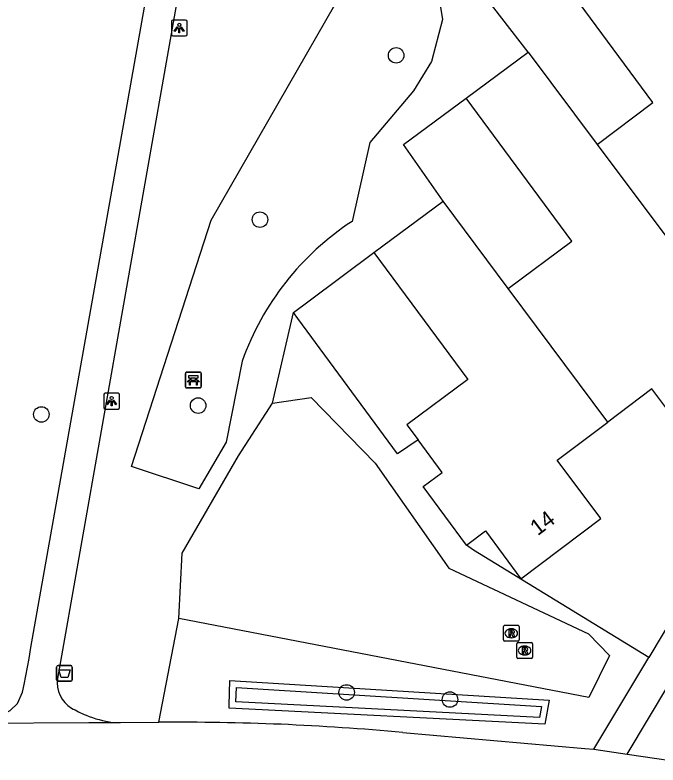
# Model space of a CAD drawing. Extents: x 163427 to 164190, y 380331 to 381641.
# Drawn here: x 163844.72 to 163885.29, y 381011.84 to 381059.16 of the extents above; entities that cross this region are included whole.
import ezdxf

# ---------------------------------------------------------------- set-up
doc = ezdxf.new("R2010")
doc.units = 0
for name, color, linetype in [('IMGEO_Afvalbak', 7, 'Continuous'), ('IMGEO_Bank', 7, 'Continuous'), ('IMGEO_Boom', 7, 'Continuous'), ('IMGEO_Fietspad_gesloten', 7, 'Continuous'), ('IMGEO_Groenvoorziening', 7, 'Continuous'), ('IMGEO_Lichtpunt', 7, 'Continuous'), ('IMGEO_Meer_plas_ven_vijver', 7, 'Continuous'), ('IMGEO_Pand', 7, 'Continuous'), ('IMGEO_Pand_nummerreeks', 7, 'Continuous'), ('IMGEO_Rioolput', 7, 'Continuous'), ('IMGEO_Voetpad_halfverhard', 7, 'Continuous'), ('IMGEO_Voetpad_open', 7, 'Continuous'), ('IMGEO_Waterloop', 7, 'Continuous')]:
    doc.layers.add(name, color=color, linetype=linetype)

msp = doc.modelspace()

# ---------------------------------------------------------------- linework, layer by layer
at = {"layer": 'IMGEO_Afvalbak'}
for p, q in [((163847.344, 381017.217), (163847.344, 381018.017)), ((163847.344, 381018.017), (163847.344, 381017.217)), ((163847.444, 381018.117), (163848.234, 381018.117)), ((163848.234, 381018.117), (163847.444, 381018.117)), ((163848.334, 381018.017), (163848.334, 381017.217)), ((163848.334, 381017.217), (163848.334, 381018.017)), ((163848.234, 381017.117), (163847.444, 381017.117)), ((163847.444, 381017.117), (163848.234, 381017.117))]:
    msp.add_line(p, q, dxfattribs=at)
msp.add_lwpolyline([(163847.487, 381017.831), (163848.191, 381017.831), (163848.042, 381017.361), (163847.636, 381017.361), (163847.487, 381017.831)], dxfattribs=at)
for centre, start, end in [((163847.444, 381018.017), 90, 180), ((163847.444, 381018.017), 90, 180), ((163848.234, 381018.017), 0, 90), ((163848.234, 381018.017), 360, 90), ((163847.444, 381017.217), 180, 270), ((163847.444, 381017.217), 180, 270), ((163848.234, 381017.217), 270, 0), ((163848.234, 381017.217), 270, 0)]:
    msp.add_arc(centre, 0.1, start, end, dxfattribs=at)
at = {"layer": 'IMGEO_Bank'}
for p, q in [((163855.469, 381035.7), (163855.469, 381036.541)), ((163855.469, 381036.541), (163855.469, 381035.7)), ((163855.544, 381036.625), (163856.385, 381036.625)), ((163856.385, 381036.625), (163855.544, 381036.625)), ((163856.469, 381036.55), (163856.469, 381035.709)), ((163856.469, 381035.709), (163856.469, 381036.55)), ((163856.166, 381036.023), (163855.773, 381036.023)), ((163855.778, 381036.131), (163855.778, 381036.237)), ((163855.822, 381036.237), (163855.822, 381036.131)), ((163856.11, 381036.243), (163855.828, 381036.243)), ((163855.828, 381036.125), (163856.11, 381036.125)), ((163856.116, 381036.131), (163856.116, 381036.237)), ((163856.16, 381036.237), (163856.16, 381036.131)), ((163856.394, 381035.625), (163855.553, 381035.625)), ((163855.553, 381035.625), (163856.394, 381035.625))]:
    msp.add_line(p, q, dxfattribs=at)
for points in [[(163855.772, 381036.243), (163855.686, 381036.243), (163855.686, 381036.404), (163856.249, 381036.404), (163856.249, 381036.243), (163856.166, 381036.243)], [(163855.716, 381036.023), (163855.574, 381036.023), (163855.686, 381036.125), (163855.772, 381036.125)], [(163855.766, 381036.016), (163855.766, 381035.809), (163855.723, 381035.809), (163855.723, 381036.016)], [(163856.166, 381036.125), (163856.249, 381036.125), (163856.361, 381036.023), (163856.222, 381036.023)], [(163856.216, 381036.016), (163856.216, 381035.809), (163856.172, 381035.809), (163856.172, 381036.016)]]:
    msp.add_lwpolyline(points, dxfattribs=at)
for centre, radius, start, end in [((163855.547, 381036.547), 0.0779, 92.4484, 184.2845), ((163855.547, 381036.547), 0.0779, 92.4484, 184.2845), ((163856.391, 381036.547), 0.0779, 2.4484, 94.2845), ((163856.391, 381036.547), 0.0779, 2.4484, 94.2845), ((163855.716, 381036.016), 0.00671, 2.8957, 87.1043), ((163855.773, 381036.016), 0.00671, 92.8957, 177.1043), ((163855.771, 381036.236), 0.00671, 2.8957, 87.1043), ((163855.771, 381036.132), 0.00671, 272.8957, 357.1043), ((163855.828, 381036.236), 0.00671, 92.8957, 177.1043), ((163855.828, 381036.132), 0.00671, 182.8957, 267.1043), ((163856.11, 381036.236), 0.00671, 2.8957, 87.1043), ((163856.11, 381036.132), 0.00671, 272.8957, 357.1043), ((163856.167, 381036.236), 0.00671, 92.8957, 177.1043), ((163856.167, 381036.132), 0.00671, 182.8957, 267.1043), ((163856.165, 381036.016), 0.00671, 2.8957, 87.1043), ((163856.222, 381036.016), 0.00671, 92.8957, 177.1043), ((163855.547, 381035.703), 0.0779, 182.4484, 274.2845), ((163855.547, 381035.703), 0.0779, 182.4484, 274.2845), ((163856.391, 381035.703), 0.0779, 272.4484, 4.2845), ((163856.391, 381035.703), 0.0779, 272.4484, 4.2845)]:
    msp.add_arc(centre, radius, start, end, dxfattribs=at)
at = {"layer": 'IMGEO_Boom'}
for centre in [(163868.764, 381056.614), (163860.172, 381046.249), (163856.273, 381034.515), (163846.384, 381033.957), (163865.641, 381016.415), (163872.161, 381015.964)]:
    msp.add_circle(centre, 0.489, dxfattribs=at)
at = {"layer": 'IMGEO_Fietspad_gesloten'}
for points in [[(163842.404, 381014.476), (163849.374, 381014.508), (163850.868, 381014.515)], [(163850.868, 381014.515), (163851.377, 381014.517), (163853.795, 381014.528)], [(163869.192, 381013.882), (163880.671, 381012.884), (163881.243, 381012.828)], [(163881.243, 381012.828), (163883.348, 381012.515)], [(163883.348, 381012.515), (163887.945, 381011.835)]]:
    msp.add_lwpolyline(points, dxfattribs=at)
msp.add_arc((163855.187, 380863.887), 150.647, 84.66566, 90.52933, dxfattribs=at)
at = {"layer": 'IMGEO_Groenvoorziening'}
for points in [[(163892.032, 381091.103), (163892.433, 381091.325), (163893.363, 381089.769), (163893.712, 381086.589), (163885.188, 381079.149), (163877.401, 381069.894), (163877.35, 381068.327), (163876.539, 381066.473), (163872.253, 381063.156), (163871.244, 381061.59), (163871.684, 381058.886), (163871, 381056.23), (163869.868, 381054.37), (163867.112, 381051.126), (163865.984, 381046.133)], [(163877.091, 381056.827), (163873.767, 381061.119), (163873.306, 381061.714), (163874.824, 381062.84), (163881.373, 381067.697), (163879.447, 381070.311), (163879.387, 381070.393), (163879.593, 381070.547), (163883.835, 381073.718)], [(163859.052, 381037.328), (163858.039, 381032.201), (163856.309, 381029.254), (163852.062, 381030.665), (163857.097, 381046.206), (163865.555, 381060.95), (163867.201, 381064.226)], [(163871.728, 381047.42), (163869.236, 381050.985), (163873.193, 381053.924)], [(163862.281, 381040.382), (163863.274, 381041.124), (163867.363, 381044.182)], [(163860.955, 381034.673), (163862.281, 381040.382)], [(163870.145, 381032.362), (163868.85, 381031.479), (163862.563, 381040), (163862.281, 381040.382)], [(163884.702, 381018.618), (163873.638, 381025.391), (163873.196, 381025.711)], [(163853.795, 381014.528), (163855.057, 381021.071)], [(163878.156, 381014.406), (163858.232, 381015.424), (163858.238, 381015.621), (163858.281, 381017.177), (163878.428, 381015.916), (163878.156, 381014.406)]]:
    msp.add_lwpolyline(points, dxfattribs=at)
msp.add_arc((163875.638, 381031.401), 17.614, 123.2384, 160.3363, dxfattribs=at)
at = {"layer": 'IMGEO_Lichtpunt'}
for p, q in [((163854.583, 381058.744), (163854.583, 381057.937)), ((163854.583, 381058.744), (163854.583, 381057.937)), ((163855.485, 381058.839), (163854.677, 381058.839)), ((163855.485, 381058.839), (163854.677, 381058.839)), ((163855.579, 381057.937), (163855.579, 381058.744)), ((163855.579, 381057.937), (163855.579, 381058.744)), ((163854.677, 381057.843), (163855.485, 381057.843)), ((163854.677, 381057.843), (163855.485, 381057.843)), ((163850.316, 381035.196), (163850.316, 381034.389)), ((163850.316, 381035.196), (163850.316, 381034.389)), ((163851.218, 381035.291), (163850.41, 381035.291)), ((163851.218, 381035.291), (163850.41, 381035.291)), ((163851.312, 381034.389), (163851.312, 381035.196)), ((163851.312, 381034.389), (163851.312, 381035.196)), ((163850.41, 381034.295), (163851.218, 381034.295)), ((163850.41, 381034.295), (163851.218, 381034.295))]:
    msp.add_line(p, q, dxfattribs=at)
for points in [[(163854.957, 381058.408), (163854.996, 381058.38), (163854.808, 381058.118), (163854.77, 381058.145), (163854.957, 381058.408)], [(163855.059, 381058.36), (163855.106, 381058.36), (163855.106, 381058.038), (163855.059, 381058.038), (163855.059, 381058.36)], [(163855.169, 381058.38), (163855.207, 381058.407), (163855.394, 381058.145), (163855.355, 381058.117), (163855.169, 381058.38)], [(163850.69, 381034.86), (163850.729, 381034.832), (163850.541, 381034.57), (163850.503, 381034.597), (163850.69, 381034.86)], [(163850.792, 381034.812), (163850.839, 381034.812), (163850.839, 381034.49), (163850.792, 381034.49), (163850.792, 381034.812)], [(163850.902, 381034.832), (163850.94, 381034.859), (163851.127, 381034.597), (163851.088, 381034.569), (163850.902, 381034.832)]]:
    msp.add_lwpolyline(points, dxfattribs=at)
for centre in [(163855.082, 381058.542), (163850.815, 381034.994)]:
    msp.add_circle(centre, 0.0994, dxfattribs=at)
for centre, start, end in [((163854.677, 381058.744), 90, 180), ((163854.677, 381058.744), 90, 180), ((163855.485, 381058.744), 0, 90), ((163855.485, 381058.744), 0, 90), ((163854.677, 381057.937), 180, 270), ((163854.677, 381057.937), 180, 270), ((163855.485, 381057.937), 270, 0), ((163855.485, 381057.937), 270, 360), ((163850.41, 381035.196), 90, 180), ((163850.41, 381035.196), 90, 180), ((163851.218, 381035.196), 0, 90), ((163851.218, 381035.196), 0, 90), ((163850.41, 381034.389), 180, 270), ((163850.41, 381034.389), 180, 270), ((163851.218, 381034.389), 270, 0), ((163851.218, 381034.389), 270, 360)]:
    msp.add_arc(centre, 0.0946, start, end, dxfattribs=at)
at = {"layer": 'IMGEO_Meer_plas_ven_vijver'}
for points in [[(163860.955, 381034.673), (163863.398, 381035.018), (163867.446, 381030.877), (163872.08, 381024.256), (163880.893, 381020.104), (163882.225, 381018.737), (163880.925, 381016.098), (163855.057, 381021.071)], [(163855.057, 381021.071), (163855.272, 381025.205), (163858.813, 381031.35), (163860.955, 381034.673)]]:
    msp.add_lwpolyline(points, dxfattribs=at)
at = {"layer": 'IMGEO_Pand'}
for points in [[(163881.446, 381050.999), (163884.971, 381053.633), (163878.533, 381062.366), (163882.919, 381065.608), (163887.001, 381060.106)], [(163873.193, 381053.924), (163877.091, 381056.827)], [(163877.091, 381056.827), (163881.446, 381050.999)], [(163875.839, 381041.903), (163879.848, 381044.89), (163873.193, 381053.924)], [(163881.446, 381050.999), (163887.731, 381042.589)], [(163867.363, 381044.182), (163871.728, 381047.42)], [(163875.839, 381041.903), (163871.728, 381047.42)], [(163867.363, 381044.182), (163873.296, 381036.157), (163869.444, 381033.309), (163870.145, 381032.362)], [(163887.731, 381042.589), (163887.641, 381042.523), (163890.954, 381038.117), (163885.779, 381034.397), (163884.902, 381035.564), (163882.12, 381033.474)], [(163882.12, 381033.474), (163875.839, 381041.903)], [(163873.196, 381025.711), (163874.402, 381026.603), (163876.631, 381023.588), (163881.689, 381027.386), (163878.921, 381031.072), (163882.12, 381033.474)], [(163873.196, 381025.711), (163870.461, 381029.41), (163871.668, 381030.302), (163870.145, 381032.362)]]:
    msp.add_lwpolyline(points, dxfattribs=at)
at = {"layer": 'IMGEO_Rioolput'}
for p, q in [((163875.53, 381019.723), (163875.53, 381020.575)), ((163875.605, 381020.649), (163876.457, 381020.649)), ((163876.018, 381020.429), (163876.043, 381020.429)), ((163876.531, 381020.575), (163876.531, 381019.723)), ((163876.041, 381019.869), (163876.016, 381019.869)), ((163876.457, 381019.649), (163875.605, 381019.649)), ((163876.371, 381018.634), (163876.371, 381019.486)), ((163876.446, 381019.56), (163877.298, 381019.56)), ((163876.859, 381019.34), (163876.884, 381019.34)), ((163877.372, 381019.486), (163877.372, 381018.634)), ((163877.298, 381018.56), (163876.446, 381018.56)), ((163876.882, 381018.78), (163876.857, 381018.78))]:
    msp.add_line(p, q, dxfattribs=at)
for points in [[(163875.53, 381019.723), (163875.53, 381020.575)], [(163875.605, 381020.649), (163876.457, 381020.649)], [(163876.119, 381020.347), (163875.867, 381020.349), (163875.867, 381019.949)], [(163876.045, 381020.268), (163875.991, 381020.268), (163875.991, 381020.187)], [(163876.531, 381020.575), (163876.531, 381019.723)], [(163875.867, 381019.949), (163875.991, 381019.949), (163875.991, 381020.111), (163876.002, 381020.111)], [(163875.991, 381020.187), (163876.043, 381020.187)], [(163876.049, 381020.082), (163876.12, 381019.949), (163876.26, 381019.949), (163876.195, 381020.075)], [(163876.457, 381019.649), (163875.605, 381019.649)], [(163876.371, 381018.634), (163876.371, 381019.486)], [(163876.446, 381019.56), (163877.298, 381019.56)], [(163877.372, 381019.486), (163877.372, 381018.634)], [(163876.96, 381019.258), (163876.708, 381019.26), (163876.708, 381018.86)], [(163876.708, 381018.86), (163876.832, 381018.86), (163876.832, 381019.022), (163876.843, 381019.022)], [(163876.886, 381019.179), (163876.832, 381019.179), (163876.832, 381019.098)], [(163876.832, 381019.098), (163876.884, 381019.098)], [(163876.89, 381018.993), (163876.961, 381018.86), (163877.101, 381018.86), (163877.036, 381018.986)], [(163877.298, 381018.56), (163876.446, 381018.56)]]:
    msp.add_lwpolyline(points, dxfattribs=at)
for centre, radius, start, end in [((163875.607, 381020.573), 0.0765, 91.552, 178.448), ((163875.607, 381020.573), 0.0765, 91.552, 178.448), ((163876.051, 381020.172), 0.0964, 77.0061, 93.1865), ((163876.065, 381020.229), 0.0378, 276.6634, 79.6772), ((163876.118, 381020.237), 0.109, 350.3612, 89.416), ((163876.455, 381020.573), 0.0765, 1.552, 88.448), ((163876.455, 381020.573), 0.0765, 1.552, 88.448), ((163876.001, 381020.058), 0.0533, 26.0293, 88.6989), ((163876.027, 381020.376), 0.19, 274.7715, 282.9687), ((163876.116, 381020.237), 0.112, 277.5842, 350.9817), ((163876.1, 381020.022), 0.108, 29.5134, 73.7905), ((163875.607, 381019.725), 0.0765, 181.552, 268.448), ((163875.607, 381019.725), 0.0765, 181.552, 268.448), ((163876.448, 381019.484), 0.0765, 91.552, 178.448), ((163876.448, 381019.484), 0.0765, 91.552, 178.448), ((163876.455, 381019.725), 0.0765, 271.552, 358.448), ((163876.455, 381019.725), 0.0765, 271.552, 358.448), ((163877.296, 381019.484), 0.0765, 1.552, 88.448), ((163877.296, 381019.484), 0.0765, 1.552, 88.448), ((163876.842, 381018.969), 0.0533, 26.0293, 88.6989), ((163876.868, 381019.287), 0.19, 274.7715, 282.9687), ((163876.892, 381019.083), 0.0964, 77.0061, 93.1865), ((163876.906, 381019.14), 0.0378, 276.6634, 79.6772), ((163876.959, 381019.148), 0.109, 350.3612, 89.416), ((163876.957, 381019.148), 0.112, 277.5842, 350.9817), ((163876.941, 381018.933), 0.108, 29.5134, 73.7905), ((163876.448, 381018.636), 0.0765, 181.552, 268.448), ((163876.448, 381018.636), 0.0765, 181.552, 268.448), ((163877.296, 381018.636), 0.0765, 271.552, 358.448), ((163877.296, 381018.636), 0.0765, 271.552, 358.448)]:
    msp.add_arc(centre, radius, start, end, dxfattribs=at)
for centre, major_axis, ratio, start_param, end_param in [((163876.017, 381020.149), (-0.387, 0.002), 0.722429, 4.712389, 7.853982), ((163876.042, 381020.149), (-0.39, 0.002), 0.717154, 1.570796, 4.712389), ((163876.858, 381019.06), (-0.387, 0.002), 0.722429, 4.712389, 7.853982), ((163876.883, 381019.06), (-0.39, 0.002), 0.717154, 1.570796, 4.712389)]:
    msp.add_ellipse(centre, major_axis=major_axis, ratio=ratio, start_param=start_param, end_param=end_param, dxfattribs=at)
at = {"layer": 'IMGEO_Voetpad_halfverhard'}
for points in [[(163842.404, 381014.476), (163843.079, 381014.688), (163843.646, 381014.894), (163844.417, 381015.282), (163844.873, 381015.706), (163845.186, 381016.426), (163845.295, 381016.916), (163845.602, 381018.56), (163845.726, 381019.254), (163855.417, 381073.893)], [(163857.272, 381073.268), (163847.391, 381017.291)]]:
    msp.add_lwpolyline(points, dxfattribs=at)
for centre, radius, start, end in [((163849.293, 381017.059), 1.916, 173.0563, 238.1857), ((163851.987, 381021.766), 7.338, 239.6837, 247.6866), ((163851.957, 381021.681), 7.248, 247.6563, 261.3629)]:
    msp.add_arc(centre, radius, start, end, dxfattribs=at)
at = {"layer": 'IMGEO_Voetpad_open'}
for points in [[(163911.288, 381063.108), (163897.12, 381039.404), (163884.702, 381018.618)], [(163883.348, 381012.515), (163888.718, 381021.511), (163890.628, 381020.363)], [(163881.243, 381012.828), (163884.702, 381018.618)]]:
    msp.add_lwpolyline(points, dxfattribs=at)
at = {"layer": 'IMGEO_Waterloop'}
msp.add_lwpolyline([(163877.935, 381015.529), (163877.811, 381014.841), (163858.66, 381015.819), (163858.685, 381016.734), (163877.935, 381015.529)], dxfattribs=at)

# ---------------------------------------------------------------- texts
at = {"layer": 'IMGEO_Pand_nummerreeks'}
msp.add_text('14', height=1, rotation=36.9042, dxfattribs=at).set_placement((163877.698, 381026.265))

doc.saveas('drawing.dxf')
